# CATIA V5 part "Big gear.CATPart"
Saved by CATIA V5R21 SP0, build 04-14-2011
Part number: Part2
Bounding box of the stored display mesh (mm): x -27.5 to 27.5, y -27.5 to 27.5, z 0 to 10
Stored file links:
  D:\CATIA V5R21 E-RESOURCES\CATIA-V5R21\catia-v5r21-prt\c16-catia-v5r20-prt\Gear Joint-(16-53)\CAT_V5R21_Big gear.CATPart
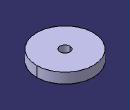
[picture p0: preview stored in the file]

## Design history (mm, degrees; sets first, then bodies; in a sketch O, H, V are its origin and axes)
Body1 (main body)
  Sketch1 on xy-plane, origin (0, 0, 0), H (1, 0, 0), V (0, 1, 0)
    circle A1 centre (0, 0) radius 27.5
    circle A2 centre (0, 0) radius 5
    radius A1 = 27.5
    radius A2 = 5
  Pad1: profile Sketch1, direction (0, 0, 1), length 10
